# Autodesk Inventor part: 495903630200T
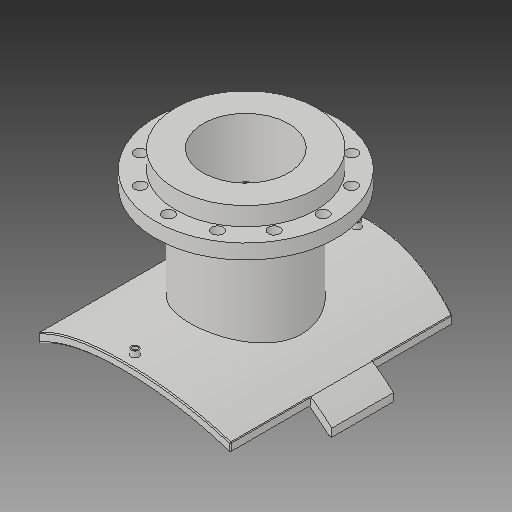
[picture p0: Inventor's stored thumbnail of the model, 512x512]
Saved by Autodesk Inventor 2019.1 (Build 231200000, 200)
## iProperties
Created: 2017-10
Part Number: 495903630200T
Material: Generic
Description: PLASSON FLANGED BRANCH SADDLE 630X200
Document SubType Name: Modeling
Designer: KIM
Mass: 2339.99 g
Surface Area: 3251.55 cm^2
Volume: 2339.99 cm^3
Density: 1 g/cm^3
Appearance: Default
Author: KIM
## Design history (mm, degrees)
derived "495904_495903.ipt"
feature "Solid1::495904_495903.ipt"
feature "Solid2::495904_495903.ipt"
tag "TaggingFeature1"
body "Solid1"
other parameters: "d1" = 15, "d2" = 364.5, "d4" = 0, "d6" = 117.5, "d7" = 0, "d12" = 340.6, "d13" = 14, "d14" = 211.5, "d16" = 5 deg, "d18" = 4, "d19" = 14, "d20" = 0, "d21" = 3, "d22" = 0, "d36" = 211.5, "d38" = 0, "d39" = 2, "d41" = 163, "d42" = 268, "d43" = 344, "d46" = 214.4, "d47" = 16, "d48" = 10.4, "d49" = 175, "d51" = 642.6, "d53" = 0, "d54" = 22, "d55" = 147.5, "d57" = 0, "d59" = 360 deg, "d61" = 28, "d63" = 0, "d67" = 15, "d68" = 125, "d70" = 0, "d71" = 2, "d72" = 405, "d_1" = 268, "B_" = 405, "x_" = 15, "D_" = 16, "DN_" = 163, "D_1" = 344, "t_" = 28, "s_" = 22, "Dp_" = 295
